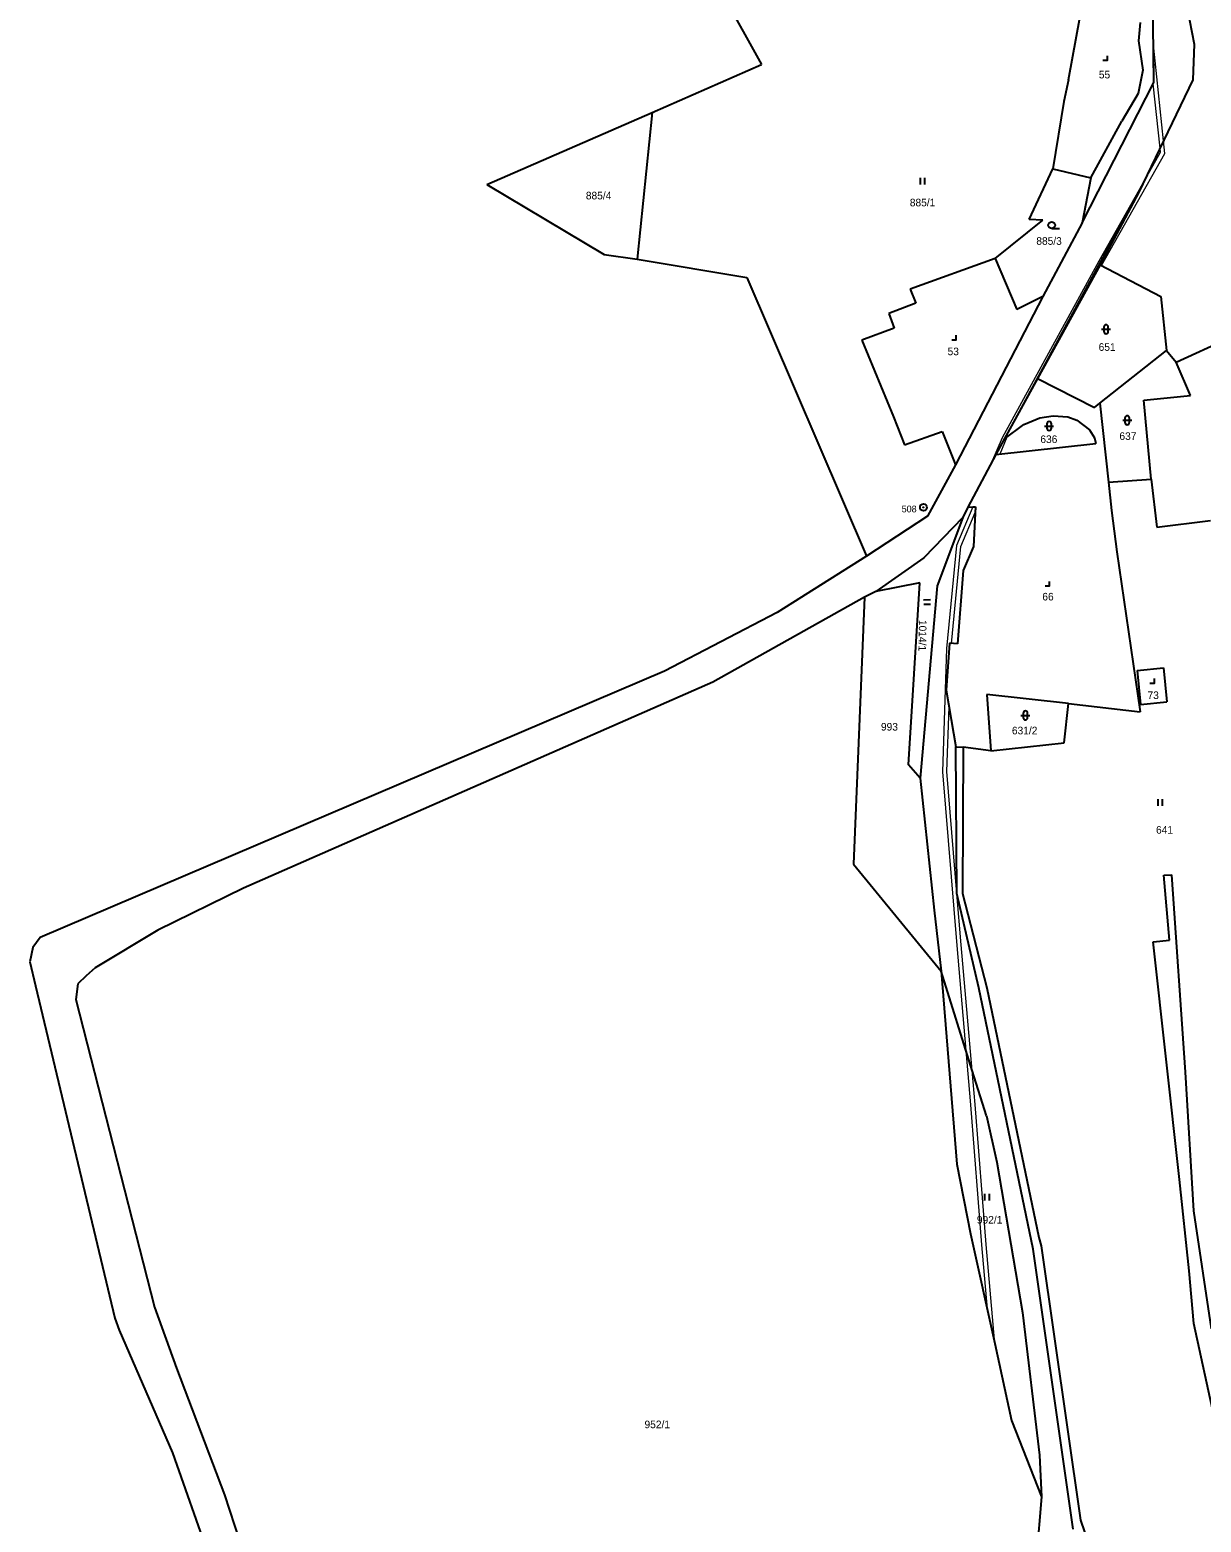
# Model space of a CAD drawing. Extents: x -744132 to -742433, y -984679 to -982287.
# Drawn here: x -743097.5 to -742836, y -983197.5 to -982864.5 of the extents above; entities that cross this region are included whole.
import ezdxf
from ezdxf.enums import TextEntityAlignment as Align

# ---------------------------------------------------------------- set-up
doc = ezdxf.new("R2010")
doc.units = 0
doc.header["$LTSCALE"] = 0.68
for name, color, linetype, lineweight in [('1', 7, 'Continuous', 25), ('13', 7, 'Continuous', 13), ('3', 7, 'Continuous', 25), ('8', 7, 'Continuous', 25)]:
    doc.layers.add(name, color=color, linetype=linetype, lineweight=lineweight)
doc.layers.add('2', color=7, linetype='Continuous')

msp = doc.modelspace()

# ---------------------------------------------------------------- linework, layer by layer
at = {"layer": '1'}
for p, q in [((-742966.53, -982813.82), (-742934.16, -982872.23)), ((-742865.59, -982875.64), (-742861.61, -982853.62)), ((-742846.57, -982876.21), (-742846.78, -982853.83)), ((-742839.96, -982855.35), (-742837.54, -982867.71)), ((-742837.54, -982867.71), (-742837.86, -982875.65)), ((-742958.53, -982882.93), (-742934.16, -982872.23)), ((-742865.59, -982875.64), (-742866.66, -982880.45)), ((-742862.57, -982907.56), (-742846.57, -982876.21)), ((-742849.03, -982873.5), (-742850.01, -982878.73)), ((-742837.86, -982875.65), (-742849.92, -982900.71)), ((-742850.01, -982878.73), (-742853.66, -982884.9)), ((-742995.42, -982898.97), (-742958.53, -982882.93)), ((-742958.53, -982882.93), (-742961.86, -982915.69)), ((-742866.66, -982880.45), (-742869.13, -982895.52)), ((-742860.6, -982897.53), (-742853.66, -982884.9)), ((-742874.36, -982906.78), (-742869.13, -982895.52)), ((-742869.13, -982895.52), (-742860.6, -982897.53)), ((-742995.42, -982898.97), (-742969.28, -982914.62)), ((-742860.6, -982897.53), (-742862.57, -982907.56)), ((-742849.92, -982900.71), (-742858.5, -982916.93)), ((-742881.97, -982915.55), (-742871.36, -982906.98)), ((-742871.36, -982906.98), (-742874.36, -982906.78)), ((-742862.57, -982907.56), (-742871.34, -982924.02)), ((-742969.28, -982914.62), (-742961.86, -982915.69)), ((-742961.86, -982915.69), (-742937.43, -982919.76)), ((-742881.97, -982915.55), (-742900.92, -982922.33)), ((-742881.97, -982915.55), (-742877.14, -982926.9)), ((-742937.43, -982919.76), (-742910.66, -982981.98)), ((-742858.5, -982916.93), (-742872.5, -982942.28)), ((-742858.5, -982916.93), (-742844.97, -982924.02)), ((-742900.92, -982922.33), (-742899.68, -982925.5)), ((-742899.68, -982925.5), (-742905.7, -982927.81)), ((-742871.34, -982924.02), (-742890.84, -982961.56)), ((-742871.34, -982924.02), (-742877.14, -982926.9)), ((-742844.97, -982924.02), (-742843.72, -982936.06)), ((-742905.7, -982927.81), (-742904.54, -982931.05)), ((-742904.54, -982931.05), (-742911.71, -982933.75)), ((-742911.71, -982933.75), (-742904.7, -982950.88)), ((-742858.63, -982947.79), (-742843.72, -982936.06)), ((-742843.72, -982936.06), (-742841.59, -982938.68)), ((-742841.59, -982938.68), (-742830.15, -982933.45)), ((-742838.35, -982946.12), (-742841.59, -982938.68)), ((-742872.5, -982942.28), (-742879.94, -982955.85)), ((-742872.5, -982942.28), (-742859.77, -982948.75)), ((-742848.8, -982947.14), (-742838.35, -982946.12)), ((-742859.77, -982948.75), (-742858.63, -982947.79)), ((-742858.63, -982947.79), (-742856.68, -982965.42)), ((-742847.15, -982964.77), (-742848.8, -982947.14)), ((-742904.7, -982950.88), (-742902.23, -982957.13)), ((-742879.94, -982955.85), (-742875.6, -982952.57)), ((-742875.6, -982952.57), (-742871.98, -982951.08)), ((-742871.98, -982951.08), (-742868.99, -982950.6)), ((-742868.99, -982950.6), (-742865.77, -982950.84)), ((-742865.77, -982950.84), (-742863.72, -982951.63)), ((-742863.72, -982951.63), (-742860.89, -982953.75)), ((-742902.23, -982957.13), (-742893.82, -982954.15)), ((-742893.82, -982954.15), (-742890.84, -982961.56)), ((-742879.94, -982955.85), (-742881.81, -982959.24)), ((-742860.89, -982953.75), (-742859.82, -982955.57)), ((-742859.82, -982955.57), (-742859.48, -982956.79)), ((-742881.81, -982959.24), (-742888.06, -982970.98)), ((-742881.81, -982959.24), (-742859.48, -982956.79)), ((-742890.84, -982961.56), (-742897.1, -982973.01)), ((-742856.68, -982965.42), (-742847.15, -982964.77)), ((-742856.68, -982965.42), (-742856, -982971.79)), ((-742847.15, -982964.77), (-742845.9, -982975.5)), ((-742897.1, -982973.01), (-742910.66, -982981.98)), ((-742888.06, -982970.98), (-742889.17, -982973.31)), ((-742888.06, -982970.98), (-742886.37, -982970.93)), ((-742856, -982971.79), (-742854.81, -982980.97)), ((-742889.17, -982973.31), (-742897.89, -982982.34)), ((-742889.17, -982973.31), (-742894.93, -982988.58)), ((-742845.9, -982975.5), (-742833.9, -982973.99)), ((-742910.66, -982981.98), (-742930.65, -982994.51)), ((-742897.89, -982982.34), (-742908.58, -982989.86)), ((-742854.81, -982980.97), (-742849.58, -983016.65)), ((-742889.08, -982985.13), (-742890.39, -983001.52)), ((-742898.77, -982987.9), (-742908.58, -982989.86)), ((-742901.31, -983028.54), (-742898.77, -982987.9)), ((-742894.93, -982988.58), (-742898.7, -983031.5)), ((-742911.14, -982991.09), (-742944.98, -983010.09)), ((-742911.14, -982991.09), (-742913.58, -983050.7)), ((-742908.58, -982989.86), (-742911.14, -982991.09)), ((-742930.65, -982994.51), (-742955.81, -983007.62)), ((-742892.16, -983001.37), (-742892.92, -983011.82)), ((-742890.39, -983001.52), (-742892.16, -983001.37)), ((-742955.81, -983007.62), (-743095.21, -983067.02)), ((-742850.29, -983007.46), (-742844.42, -983006.84)), ((-742850.29, -983007.46), (-742849.49, -983015.08)), ((-742844.42, -983006.84), (-742843.62, -983014.46)), ((-742944.98, -983010.09), (-743049.76, -983056.04)), ((-742892.92, -983011.82), (-742890.73, -983024.47)), ((-742883.82, -983012.8), (-742882.9, -983025.42)), ((-742865.57, -983014.85), (-742883.82, -983012.8)), ((-742866.59, -983023.58), (-742865.57, -983014.85)), ((-742865.57, -983014.85), (-742849.58, -983016.65)), ((-742849.49, -983015.08), (-742843.62, -983014.46)), ((-742890.73, -983024.47), (-742889.14, -983024.57)), ((-742890.5, -983057.22), (-742890.73, -983024.47)), ((-742889.14, -983024.57), (-742889.29, -983057.24)), ((-742882.9, -983025.42), (-742889.14, -983024.57)), ((-742882.9, -983025.42), (-742866.59, -983023.58)), ((-742898.7, -983031.5), (-742901.31, -983028.54)), ((-742898.7, -983031.5), (-742895.62, -983060.92)), ((-742913.58, -983050.7), (-742894.05, -983074.53)), ((-742844.3, -983053.12), (-742842.56, -983053.08)), ((-742843.06, -983067.67), (-742844.3, -983053.12)), ((-742839.47, -983097.08), (-742842.56, -983053.08)), ((-743049.76, -983056.04), (-743068.93, -983065.4)), ((-742885.59, -983078.24), (-742890.5, -983057.22)), ((-742889.29, -983057.24), (-742883.85, -983078.25)), ((-742895.62, -983060.92), (-742894.05, -983074.53)), ((-743068.93, -983065.4), (-743082.91, -983073.84)), ((-743096.78, -983069.29), (-743097.48, -983072.44)), ((-743095.21, -983067.02), (-743096.78, -983069.29)), ((-742846.7, -983068), (-742843.06, -983067.67)), ((-742840.85, -983121.04), (-742846.7, -983068)), ((-743097.48, -983072.44), (-743096.25, -983077.86)), ((-743084.88, -983075.56), (-743086.73, -983077.4)), ((-743082.91, -983073.84), (-743084.88, -983075.56)), ((-742894.05, -983074.53), (-742890.51, -983117.62)), ((-743096.25, -983077.86), (-743078.5, -983152.02)), ((-743086.73, -983077.4), (-743087.19, -983080.87)), ((-742873.51, -983136.56), (-742885.59, -983078.24)), ((-742883.85, -983078.25), (-742872.2, -983134.02)), ((-743087.19, -983080.87), (-743069.64, -983149.53)), ((-742837.63, -983128.02), (-742839.47, -983097.08)), ((-742883.94, -983106.86), (-742881.63, -983117.17)), ((-742890.51, -983117.62), (-742887.48, -983133.17)), ((-742881.63, -983117.17), (-742875.84, -983150.75)), ((-742838.67, -983141.42), (-742840.85, -983121.04)), ((-742833.69, -983154.35), (-742837.63, -983128.02)), ((-742887.48, -983133.17), (-742882.07, -983157.65)), ((-742872.2, -983134.02), (-742871.69, -983135.82)), ((-742871.69, -983135.82), (-742862.92, -983197.05)), ((-742864.59, -983199.1), (-742873.51, -983136.56)), ((-742837.62, -983153.2), (-742838.67, -983141.42)), ((-743069.64, -983149.53), (-743064.76, -983163.16)), ((-743078.5, -983152.02), (-743077.56, -983154.66)), ((-742875.84, -983150.75), (-742872.07, -983182.53)), ((-743077.56, -983154.66), (-743065.66, -983182.05)), ((-742833.08, -983174.04), (-742837.62, -983153.2)), ((-742882.07, -983157.65), (-742878.32, -983174.83)), ((-743064.76, -983163.16), (-743054.03, -983191.38)), ((-742878.32, -983174.83), (-742871.62, -983191.87)), ((-743065.66, -983182.05), (-743057.07, -983206.33)), ((-742872.07, -983182.53), (-742871.62, -983191.87)), ((-743054.03, -983191.38), (-743029.31, -983266.43)), ((-742871.62, -983191.87), (-742875.11, -983232.95)), ((-742862.92, -983197.05), (-742855.66, -983218))]:
    msp.add_line(p, q, dxfattribs=at)
for points in [[(-742849.6, -982862.85), (-742849.96, -982866.95), (-742849.03, -982873.5)], [(-742886.37, -982970.93), (-742886.79, -982979.76), (-742889.08, -982985.13)], [(-742883.94, -983106.86), (-742887.11, -983096.71), (-742894.05, -983074.53)]]:
    msp.add_lwpolyline(points, dxfattribs=at)
at = {"layer": '13'}
for points in [[(-742844.39, -982889.23), (-742846.65, -982867.85), (-742846.57, -982876.21), (-742846.74, -982876.54), (-742845.21, -982890.93)], [(-742858.24, -982917.07), (-742844.09, -982892.11), (-742844.39, -982889.23), (-742845.21, -982890.93), (-742845.11, -982891.89), (-742848.84, -982898.46), (-742849.92, -982900.71), (-742858.5, -982916.93)], [(-742882.77, -982961.04), (-742848.84, -982898.46), (-742858.85, -982916.11), (-742880.42, -982955.51)], [(-742879.26, -982955.34), (-742879.94, -982955.85), (-742881.81, -982959.24), (-742880.88, -982959.14)], [(-742889.65, -982979.8), (-742886.43, -982972.22), (-742886.37, -982970.93), (-742886.98, -982970.95), (-742890.63, -982979.55), (-742892.84, -983002.55), (-742893.75, -983030.04), (-742890.53, -983068.79), (-742888.5, -983092.27), (-742887.46, -983104.36), (-742885, -983135.61), (-742883.77, -983149.98), (-742882.07, -983157.65), (-742884, -983135.53), (-742886.46, -983104.28), (-742887.11, -983096.71), (-742889.53, -983068.71), (-742890.5, -983057.22), (-742892.75, -983030.02), (-742892.27, -983015.57), (-742892.92, -983011.82), (-742892.16, -983001.37), (-742891.72, -983001.41)]]:
    msp.add_lwpolyline(points, close=True, dxfattribs=at)
at = {"layer": '3'}
for p, q in [((-742898.651, -982898.99), (-742898.651, -982897.49)), ((-742897.65, -982898.99), (-742897.65, -982897.49)), ((-742869.353, -982908.84), (-742867.603, -982908.84)), ((-742858.211, -982931.301), (-742856.209, -982931.301)), ((-742857.711, -982930.801), (-742857.711, -982931.802)), ((-742856.709, -982931.802), (-742856.709, -982930.801)), ((-742870.921, -982952.901), (-742868.919, -982952.901)), ((-742870.421, -982952.401), (-742870.421, -982953.402)), ((-742869.419, -982953.402), (-742869.419, -982952.401)), ((-742853.491, -982951.601), (-742851.489, -982951.601)), ((-742852.991, -982951.101), (-742852.991, -982952.102)), ((-742851.989, -982952.102), (-742851.989, -982951.101)), ((-742897.939, -982991.659), (-742896.439, -982991.633)), ((-742897.921, -982992.66), (-742896.422, -982992.634)), ((-742876.221, -983017.491), (-742874.219, -983017.491)), ((-742875.721, -983016.991), (-742875.721, -983017.992)), ((-742874.719, -983017.992), (-742874.719, -983016.991)), ((-742845.611, -983037.67), (-742845.611, -983036.17)), ((-742844.61, -983037.67), (-742844.61, -983036.17)), ((-742884.251, -983125.71), (-742884.251, -983124.21)), ((-742883.25, -983125.71), (-742883.25, -983124.21))]:
    msp.add_line(p, q, dxfattribs=at)
for points in [[(-742857.901, -982871.27), (-742856.9, -982871.27), (-742856.9, -982870.27)], [(-742891.671, -982933.65), (-742890.67, -982933.65), (-742890.67, -982932.65)], [(-742870.811, -982988.57), (-742869.81, -982988.57), (-742869.81, -982987.57)], [(-742847.431, -983010.26), (-742846.43, -983010.26), (-742846.43, -983009.26)]]:
    msp.add_lwpolyline(points, dxfattribs=at)
msp.add_circle((-742869.3529, -982908.0898), 0.75, dxfattribs=at)
for centre, start, end in [((-742857.21, -982930.8009), 0, 180), ((-742857.21, -982931.8009), 180, 359.98789), ((-742869.92, -982952.4009), 0, 180), ((-742852.49, -982951.1009), 0, 180), ((-742852.49, -982952.1009), 180, 359.98789), ((-742869.92, -982953.4009), 180, 359.98789), ((-742875.22, -983016.9909), 0, 180), ((-742875.22, -983017.9909), 180, 359.98789)]:
    msp.add_arc(centre, 0.5, start, end, dxfattribs=at)
at = {"layer": '8'}
for radius in [0.75, 0.03]:
    msp.add_circle((-742898, -982971.0498), radius, dxfattribs=at)

# ---------------------------------------------------------------- texts
at = {"layer": '2'}
for s, p in [('55', (-742858.82, -982875.335)), ('885/4', (-742973.35, -982902.335)), ('885/1', (-742901.02, -982903.875)), ('885/3', (-742872.78, -982912.465)), ('53', (-742892.59, -982937.105)), ('651', (-742858.87, -982936.125)), ('636', (-742871.88, -982956.695)), ('637', (-742854.23, -982956.005)), ('66', (-742871.44, -982991.825)), ('73', (-742847.95, -983013.825)), ('993', (-742907.47, -983020.865)), ('631/2', (-742878.23, -983021.705)), ('641', (-742846.06, -983043.875)), ('992/1', (-742886.05, -983130.885)), ('952/1', (-742960.25, -983176.545))]:
    msp.add_text(s, height=1.7, dxfattribs=at).set_placement(p)
msp.add_text('1014/1', height=1.7, rotation=269, dxfattribs=at).set_placement((-742898.974, -982996.162))
at = {"layer": '8'}
msp.add_text('508', height=1.5, dxfattribs=at).set_placement((-742899.499, -982972.167), align=Align.RIGHT)

doc.saveas('drawing.dxf')
